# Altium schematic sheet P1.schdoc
size 297 x 209 mm; Symbol: Drawing-Symbol_A4; Company: 嘉立创EDA; Version: V1.0; Page Size: A4; @Project Name: 48v-24v-12v-5v四级降压电路; @Update Date: 2026-08-21; @Create Date: 2026-08-21; Device: Drawing-Symbol_A4; @Board Name: Board1; @Page Name: P1; @Create Time: 11:02:59; @Page Count: 1; @Page No: 1; @Schematic Name: Schematic1; @Update Time: 11:02:59; @Assembly Variant: Basic; Border: 1; Title Block Position: 3; Size: A4; Width: 1170; Height: 825; Region Start: 1; X Region Count: 6; Y Region Count: 4; Blade Width: 10
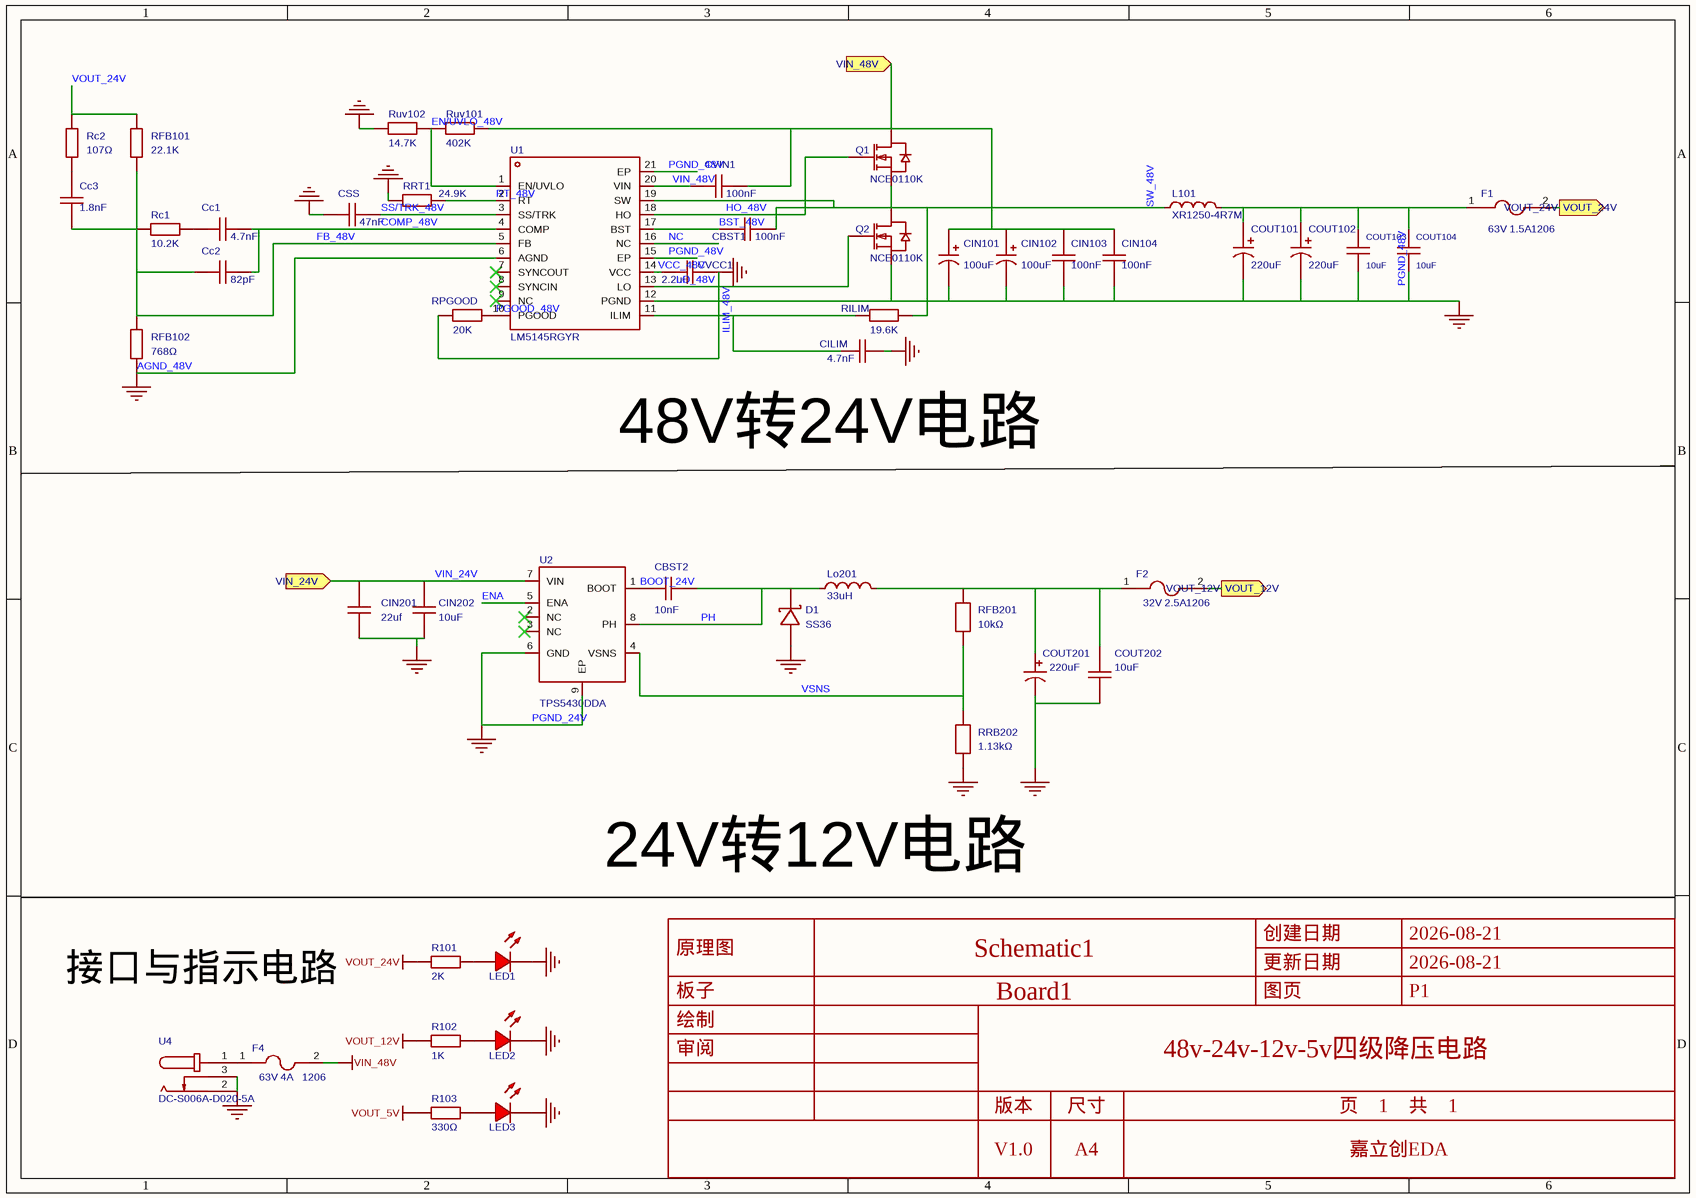
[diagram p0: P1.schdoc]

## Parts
CBST1  100nF  [C0603]
CBST2  10nF  [C0805]
Cc1  4.7nF  [C0603]
Cc2  82pF  [C0603]
Cc3  1.8nF  [C0603]
CILIM  4.7nF  [C0603]
CIN101  100uF  [CAP-SMD_BD12.5-L13.0-W13.0-LS13.7-FD]
CIN102  100uF  [CAP-SMD_BD12.5-L13.0-W13.0-LS13.7-FD]
CIN103  100nF  [C0603]
CIN104  100nF  [C0603]
CIN201  22uf  [C1206]
CIN202  10uF  [C1206]
COUT101  220uF  [CAP-SMD_BD10.0-L10.3-W10.3-LS11.7-FD]
COUT102  220uF  [CAP-SMD_BD10.0-L10.3-W10.3-LS11.7-FD]
COUT103  10uF  [C1206]
COUT104  10uF  [C1206]
COUT201  220uF  [CAP-SMD_BD8.0-L8.3-W8.3-LS9.3-FD-A]
COUT202  10uF  [C0805]
CSS  47nF  [C0603]
CVCC1  2.2uF  [C0603]
CVIN1  100nF  [C0603]
D1  SS36  [SMA_L4.3-W2.6-LS5.2-RD]
F1  Voltage Rating (DC): 63V  Current Rating: 1.5A  Supplier Footprint: 1206  [F1206]  (hidden comment: JFC1206-1300FS)
F2  Supplier Footprint: 1206  Current Rating: 2.5A  Voltage Rating (DC): 32V  [F1206]  (hidden comment: JFC1206-1300FS)
F4  Supplier Footprint: 1206  Current Rating: 4A  Voltage Rating (DC): 63V  [F1206]  (hidden comment: JFC1206-1300FS)
L101  XR1250-4R7M  [IND-SMD_L13.5-W12.6]
LED1  (no value)  [LED-TH_5mm]
LED2  (no value)  [LED-TH_5mm]
LED3  (no value)  [LED-TH_5mm]
Lo201  33uH  [IND-SMD_L8.2-W8.2-LS8.6]
Q1  NCE0110K  [TO-252-2_L6.6-W6.1-P4.57-LS9.9-TL-CW]
Q2  NCE0110K  [TO-252-2_L6.6-W6.1-P4.57-LS9.9-TL-CW]
R101  2K  [R0603]
R102  1K  [R0603]
R103  330Ω  [R0603]
Rc1  10.2K  [R0603]
Rc2  107Ω  [R0603]
RFB101  22.1K  [R0603]
RFB102  768Ω  [R0603]
RFB201  10kΩ  [R0603]
RILIM  19.6K  [R0805]
RPGOOD  20K  [R0603]
RRB202  1.13kΩ  [R0603]
RRT1  24.9K  [R0603]
Ruv101  402K  [R0603]
Ruv102  14.7K  [R0603]
U1  LM5145RGYR  [VQFN-20_L4.5-W3.5-P0.50-BL-EP]
U2  TPS5430DDA  [ESOP-8_L4.9-W3.9-P1.27-LS6.0-BL-EP-2]
U4  DC-S006A-D020-5A  [CONN-TH_DC-S006A-D020-5A]

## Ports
VIN_24V (in), VIN_48V (in), VOUT_12V (out), VOUT_24V (out)

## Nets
AGND_48V: CILIM.2 CIN101.2 CIN102.2 CIN103.1 CIN104.1 CIN201.1 CIN202.1 COUT101.2 COUT102.2 COUT103.1 COUT104.1 COUT201.2 COUT202.1 CSS.1 CVCC1.2 D1.2(A) LED1.2(A) LED2.2(A) LED3.2(A) Q2.3(S) RFB102.2 RPGOOD.1 RRB202.1 RRT1.1 Ruv102.1 U1.6(AGND) U1.12(PGND) U1.15(EP) U1.21(EP) U2.6(GND) U2.9(EP) U4.2 U4.3  [also labelled GND, PGND_24V, PGND_48V]
VIN_48V: CVIN1.1 F4.2 U1.20(VIN)
VOUT_5V: R103.1
VOUT_12V: F2.2 R102.1 ; port VOUT_12V
VOUT_24V: F1.2 R101.1 Rc2.2 RFB101.2 ; port VOUT_24V
BOOT_24V: CBST2.1 U2.1(BOOT)
BST_48V: CBST1.1 U1.17(BST)
COMP_48V: Cc1.2 Cc2.2 U1.4(COMP)
EN/UVLO_48V: Ruv101.1 Ruv102.2 U1.1(EN/UVLO)
ENA: U2.5(ENA)
FB_48V: Cc2.1 Cc3.1 Rc1.2 RFB101.1 RFB102.1 U1.5(FB)
HO_48V: Q1.1(G) U1.18(HO)
ILIM_48V: CILIM.1 RILIM.1 U1.11(ILIM)
LO_48V: Q2.1(G) U1.13(LO)
NC: U1.16(NC)
PGOOD_48V: RPGOOD.2 U1.10(PGOOD)
PH: CBST2.2 D1.1(K) Lo201.1 U2.8(PH)
RT_48V: RRT1.2 U1.2(RT)
SS/TRK_48V: CSS.2 U1.3(SS/TRK)
SW_48V: CBST1.2 L101.1 Q1.3(S) Q2.2(D) RILIM.2 U1.19(SW)
VCC_48V: CVCC1.1 U1.14(VCC)
VIN_24V: CIN201.2 CIN202.2 U2.7(VIN) ; port VIN_24V
VIN_48V: CIN101.1 CIN102.1 CIN103.2 CIN104.2 CVIN1.2 Q1.2(D) Ruv101.2 ; port VIN_48V  [a separate net that carries the same name]
VSNS: RFB201.1 RRB202.2 U2.4(VSNS)
NetCc1_1: Cc1.1 Rc1.1
NetCc3_2: Cc3.2 Rc2.1
NetCOUT101_1: COUT101.1 COUT102.1 COUT103.2 COUT104.2 F1.1 L101.2
NetCOUT201_1: COUT201.1 COUT202.2 F2.1 Lo201.2 RFB201.2
NetF4_1: F4.1 U4.1
NetLED1_1: LED1.1(C) R101.2
NetLED2_1: LED2.1(C) R102.2
NetLED3_1: LED3.1(C) R103.2

Not connected (* = marked no-connect by the designer): U1 7(SYNCOUT)* 8(SYNCIN)* 9(NC)*; U2 2(NC)* 3(NC)*

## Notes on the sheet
- (near CILIM) 48V转24V电路
- 24V转12V电路
- 接口与指示电路

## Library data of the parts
CBST1 CVCC1 = CAP_0603: Symbol: Capacitance; ConvertToPcb: yes; ModelId: ac125912035d415993ca9572d50418b10819f05c4eef4c71ace90d822a990e87; ModelName: C0603_L1.6-W0.8-H0.8; ModelTransform: 62.992,31.496,0,0,0,0,0,0,0
CBST2 = CAP_0805: Symbol: Capacitance; 3D Model: 1ba041120af144c991958decab20d2410819f05c4eef4c71ace90d822a990e87; 3D Model Transform: 78.74,51.181,0,0,0,0,0,0.0005,0; ConvertToPcb: yes; ModelName: C0805_L2.0-W1.3-H1.3
Cc1-Cc3 CSS = CAP_0603: Symbol: Capacitance; 3D Model: ac125912035d415993ca9572d50418b10819f05c4eef4c71ace90d822a990e87; 3D Model Transform: 62.992,31.496,0,0,0,0,0,0,0; ConvertToPcb: yes; ModelName: C0603_L1.6-W0.8-H0.8
CILIM = CC0603JRNPO9BN120: 容值:12pF;精度:±5%;额定电压:50V;温度系数:NP0;; Manufacturer: YAGEO(国巨); AddInBom: yes; ModelId: ac125912035d415993ca9572d50418b10819f05c4eef4c71ace90d822a990e87; ModelName: C0603_L1.6-W0.8-H0.8; ModelTransform: 62.992,31.496,0,0,0,0,0,0,0; Tolerance: ±5%; Voltage Rating: 50V; Temperature Coefficient: NP0
CIN101 CIN102 = JVJ100V100M12X13: 容值:100uF;精度:±20%;额定电压:100V;纹波电流:380mA@120Hz;; Manufacturer: JIERR(捷而瑞); AddInBom: yes; ModelId: 6392bc9430a7457794798829c6f113710819f05c4eef4c71ace90d822a990e87; ModelTransform: 539.369,511.81,0,180,0,0,0,0,0; Tolerance: ±20%; Voltage Rating: 100V; Lifetime: 2000hrs@105℃
CIN103 CIN104 = CC0603KRX7R0BB104: 容值:100nF;精度:±10%;额定电压:100V;温度系数:X7R;; Manufacturer: YAGEO(国巨); AddInBom: yes; ModelId: ac125912035d415993ca9572d50418b10819f05c4eef4c71ace90d822a990e87; ModelName: C0603_L1.6-W0.8-H0.8; ModelTransform: 62.992,31.496,0,0,0,0,0,0,0; Tolerance: ±10%; Voltage Rating: 100V; Temperature Coefficient: X7R
CIN201 CIN202 = CL31Y106KBKVPNE: 容值:10uF;精度:±10%;额定电压:50V;温度系数:X7S;; Manufacturer: SAMSUNG(三星); AddInBom: yes; ModelId: e4be705b945545a48e666415e3682bd80819f05c4eef4c71ace90d822a990e87; ModelName: C1206_L3.2-W1.6-H1.3; ModelTransform: 125.984,62.992,0,0,0,0,0,0,0; Tolerance: ±10%; Voltage Rating: 50V; Temperature Coefficient: X7S
COUT101 COUT102 = JVJ50V220M10x10: 容值:220uF;精度:±20%;额定电压:50V;纹波电流:220mA@120Hz;; Manufacturer: JIERR(捷而瑞); AddInBom: yes; ModelId: 50f22ba8977a4cb2b51f8d950fa665c30819f05c4eef4c71ace90d822a990e87; ModelTransform: 456.692,405.511,0,0,0,0,0,0,0; Tolerance: ±20%; Voltage Rating: 50V; Lifetime: 2000hrs@105℃
COUT103 COUT104 = CL31A106KBHNNNE: 容值:10uF;精度:±10%;额定电压:50V;温度系数:X5R;; Manufacturer: SAMSUNG(三星); AddInBom: yes; ModelId: e4be705b945545a48e666415e3682bd80819f05c4eef4c71ace90d822a990e87; ModelName: C1206_L3.2-W1.6-H1.3; ModelTransform: 125.984,62.992,0,0,0,0,0,0,0; Tolerance: ±10%; Voltage Rating: 50V; Temperature Coefficient: X5R
COUT201 = 35TZV220M8X10.5: 容值:220uF;精度:±20%;额定电压:35V;纹波电流:360mA@120Hz;等效串联电阻(ESR):-;; Manufacturer: Rubycon(红宝石); 3D Model: 557a0f6c1da54cb18f8d6716595fa7ad0819f05c4eef4c71ace90d822a990e87; 3D Model Transform: 354.33,326.771,0,180,0,0,0,0,0; Tolerance: ±20%; Voltage Rating: 35V; Lifetime: 2000hrs@105℃; AddInBom: yes
COUT202 = HGC0805R7106K250NSLJ: 容值:10uF;精度:±10%;额定电压:25V;温度系数:X7R;; Manufacturer: Chinocera(华瓷); AddInBom: yes; ModelId: 1ba041120af144c991958decab20d2410819f05c4eef4c71ace90d822a990e87; ModelName: C0805_L2.0-W1.3-H1.3; ModelTransform: 78.74,51.181,0,0,0,0,0,0.0005,0; Tolerance: ±10%; Voltage Rating: 25V; Temperature Coefficient: X7R
CVIN1 = CL10B104KC8NNNC: 容值:100nF;精度:±10%;额定电压:100V;温度系数:X7R;; Manufacturer: SAMSUNG(三星); AddInBom: yes; ModelId: ac125912035d415993ca9572d50418b10819f05c4eef4c71ace90d822a990e87; ModelName: C0603_L1.6-W0.8-H0.8; ModelTransform: 62.992,31.496,0,0,0,0,0,0,0; Tolerance: ±10%; Voltage Rating: 100V; Temperature Coefficient: X7R
D1 = SS36_C16015: 二极管配置:独立式;正向压降(Vf):700mV@3A;直流反向耐压(Vr):60V;整流电流:3A;; Manufacturer: MDD(辰达半导体); AddInBom: yes; ModelId: e3551acb3c5a4975a5e9d36087fe1fa20819f05c4eef4c71ace90d822a990e87; ModelTransform: 185.039,102.362,0,0,0,0,0,0,0; Diode Configuration: 独立式; Voltage - DC Reverse(Vr): 60V; Current - Rectified: 3A; Reverse Leakage Current (Ir): 500uA@60V; Operating Junction Temperature Range: -55℃~+125℃
F1 F4 = JFC1206-1300FS: 类型:贴片式保险丝;额定电流:3A;额定电压 (AC):63V;额定电压:63V;分断能力:50A;; Manufacturer: JDTfuse(集电通); AddInBom: yes; ModelId: f1628daad26847a79b887277a2bc85410819f05c4eef4c71ace90d822a990e87; ModelName: F1206_L3.2-W1.7-H0.6; ModelTransform: 125.984,66.929,0,0,0,0,0,0,0; Type: 贴片式保险丝; Melting I2t: 1.39; Interrupt Rating: 50A
F2 = JFC1206-1300FS: 类型:贴片式保险丝;额定电流:3A;额定电压 (AC):63V;额定电压:63V;分断能力:50A;; Manufacturer: JDTfuse(集电通); AddInBom: yes; ModelId: f1628daad26847a79b887277a2bc85410819f05c4eef4c71ace90d822a990e87; ModelName: F1206_L3.2-W1.7-H0.6; ModelTransform: 125.984,66.929,0,0,0,0,0,0,0; Type: 贴片式保险丝; Voltage Rating (AC): 63V; Melting I2t: 1.39; Interrupt Rating: 50A
L101 = XR1250-4R7M: 特性：高额定电流。频率高达 3 MHz。最高总温度工作为 125°C。低磁芯损耗。由于模制结构,超低嗡嗡声。无卤且符合 ROHS 标准。应用：笔记本电脑和个人电脑。交换机和服务器。基站。DC/DC 转换器。电池供电设备。SSD 模块; Manufacturer: XR(祥如); AddInBom: yes; ModelId: 987385deb45846018dca7f0b79c9d31d0819f05c4eef4c71ace90d822a990e87; ModelName: IND-SMD_L13.5-W12.6-H5.0; ModelTransform: 529.5265,496.062,0,0,0,0,0,0,0
LED1 = LED_TH-R_5mm: ConvertToPcb: yes; ModelId: fe9cea1bdf7642cd8d9a5077ed0e2b580819f05c4eef4c71ace90d822a990e87; ModelName: LED-TH_BD5.9-P2.54-RD_RED; ModelTransform: 222.16,238.98,581.81,180,0,0,-6,0,-220
LED2 LED3 = LED_TH-R_5mm: 3D Model: fe9cea1bdf7642cd8d9a5077ed0e2b580819f05c4eef4c71ace90d822a990e87; 3D Model Transform: 222.16,238.98,581.81,180,0,0,-6,0,-220; ConvertToPcb: yes; ModelName: LED-TH_BD5.9-P2.54-RD_RED
Lo201 = IHLP3232DZER100M11: 电感值:10uH;精度:±20%;额定电流:5.4A;饱和电流(Isat):6.4A;; Manufacturer: VISHAY(威世); AddInBom: yes; ModelId: c538bf11b7ad499ab79eaf9385e155e10819f05c4eef4c71ace90d822a990e87; ModelTransform: 340.1568,322.44,0,0,0,0,0,0,0; Tolerance: ±20%; Current Rating: 5.4A; Current - Saturation(Isat): 6.4A; DC Resistance(DCR): 51.8mΩ
Q1 Q2 = NCE0110K: 数量:1个N沟道;漏源电压(Vdss):100V;连续漏极电流(Id):9.6A;导通电阻(RDS(on)):140mΩ@10V;耗散功率(Pd):30W;阈值电压(Vgs(th)):2.5V;; Manufacturer: NCE(无锡新洁能); AddInBom: yes; ModelId: ce57f84d66384067af8a68020b6de06d0819f05c4eef4c71ace90d822a990e87; ModelName: TO-252-2L-3P_L6.6-W6.1-H2.3-LS10.1-P4.6; ModelTransform: 259.842,390.52442,0,270,0,0,38.027,-0.598,0; Number: 1个N沟道; Drain to Source Voltage: 100V; Current - Continuous Drain(Id): 9.6A; Pd - Power Dissipation: 30W; Gate Threshold Voltage (Vgs(th)): 2.5V; Gate Charge(Qg): 15.5nC; Input Capacitance(Ciss): 690pF; Reverse Transfer Capacitance (Crss@Vds): 90pF; Type: N沟道; Output Capacitance(Coss): 120pF; Vgs: ±20V
R101 RRT1 = Res_0603: Symbol: 电阻; ConvertToPcb: yes; ModelId: fc143cca1e79419f9cd78b61e9279f080819f05c4eef4c71ace90d822a990e87; ModelTransform: 31.8897,63.7794,0,90,0,0,0,0,0
R102 R103 Rc1 Rc2 RFB101 RFB102 RPGOOD Ruv101 Ruv102 = Res_0603: Symbol: 电阻; 3D Model: fc143cca1e79419f9cd78b61e9279f080819f05c4eef4c71ace90d822a990e87; 3D Model Transform: 31.8897,63.7794,0,90,0,0,0,0,0; ConvertToPcb: yes
RFB201 RRB202 = FRC0603F1001TS: 电阻类型:厚膜电阻;阻值:1kΩ;精度:±1%;功率:100mW;工作电压:75V;温度系数:±100ppm/℃;; Manufacturer: FOJAN(富捷); AddInBom: yes; ModelId: fc143cca1e79419f9cd78b61e9279f080819f05c4eef4c71ace90d822a990e87; ModelTransform: 31.8897,63.7794,0,90,0,0,0,0,0; Tolerance: ±1%; Power(Watts): 100mW; Voltage-Supply(Max): 75V
RILIM = Res_0805: Symbol: 电阻; 3D Model: 37a81e68749a4138bd2dfa6897b24b850819f05c4eef4c71ace90d822a990e87; 3D Model Transform: 78.74,51.181,0,0,0,0,0,-0.0005,0; ConvertToPcb: yes; ModelName: R0805_L2.0-W1.3-H0.6
U1 = LM5145RGYR: 功能类型:降压型;工作电压:6V~75V;输出电压:800mV~60V;输出电流:-;输出类型:可调;; Manufacturer: TI(德州仪器); AddInBom: yes; ModelId: 1552b4df8c4f41af8431dd9c7cd873a30819f05c4eef4c71ace90d822a990e87; ModelName: VQFN-20_L4.5-W3.5-H1.0-P0.50-BL-EP; ModelTransform: 137.795,177.165,0,90,0,0,0,0,0; Function: 降压型; Voltage - Supply: 6V~75V; Frequency - Switching: 1MHz; Synchronous Rectifier: 是; Number of Outputs: 1; Topology: 降压式; Quiescent Current: 1.8mA; Switch tube (built-in/external): 外置; Output Type: 可调
U2 = TPS5430DDA: 功能类型:降压型;工作电压:5.5V~36V;输出电压:1.221V~32.04V;输出电流:3A;输出类型:可调;; Manufacturer: TI(德州仪器); AddInBom: yes; ModelId: 0078439d9e964752ad4b3f828dcb56640819f05c4eef4c71ace90d822a990e87; ModelTransform: 192.913,236.22,0,0,0,0,0,0,0; Function: 降压型; Output Current: 3A; Frequency - Switching: 500kHz; Synchronous Rectifier: 否; Number of Outputs: 1; Topology: 降压式; Quiescent Current: 4.4mA; Switch tube (built-in/external): 内置; Output Type: 可调
U4 = DC-S006A-D020-5A: 连接器类型:DC电源插座;安装方式:弯插;触点内径:2mm;触点外径:6.4mm;额定电流:5A;额定电压:60V;工作温度:-40℃~+85℃;; Manufacturer: G-Switch(品赞); AddInBom: yes; Connector Type: DC电源插座; Inside Contact Diameter: 2mm; Outside Contact Diameter: 6.4mm; Current Rating: 5A; Voltage Rating (Max): 60V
